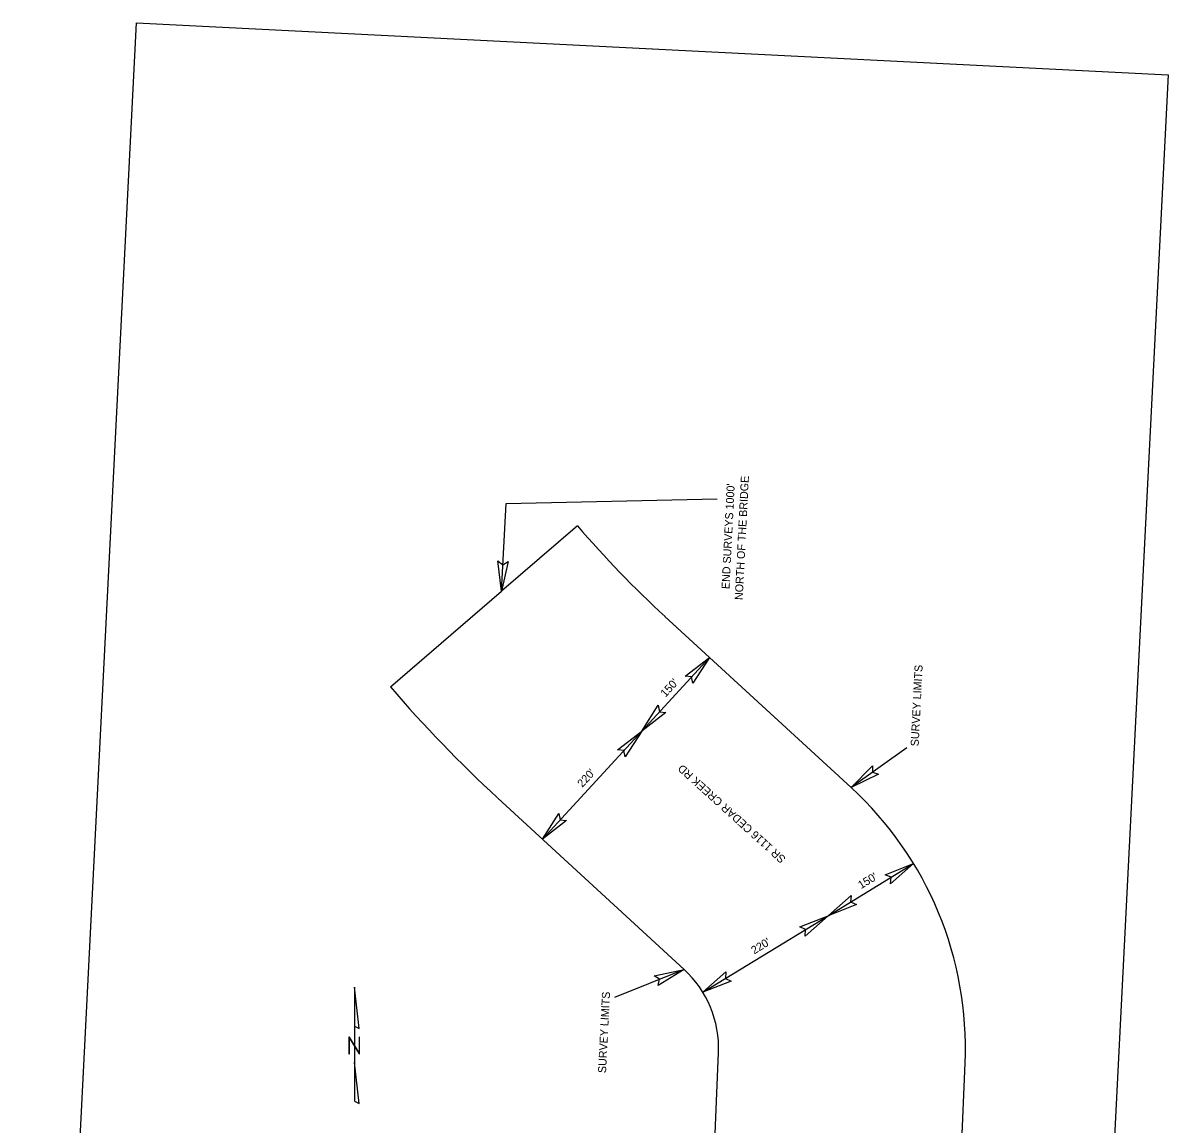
# Model space of a CAD drawing. Extents: x 2166842 to 2171409, y 841731 to 901457.
# Drawn here: x 2166842 to 2168559, y 843530 to 845181 of the extents above; entities that cross this region are included whole.
import ezdxf

# ---------------------------------------------------------------- set-up
doc = ezdxf.new("R2010")
doc.units = 0
doc.layers.add('Default', color=7, linetype='Continuous')
doc.layers.add('Prop Terminator CELL', color=7, linetype='Continuous')

# ---------------------------------------------------------------- blocks, each defined once
blk = doc.blocks.new('CTL NORTH ARROW')
at = {"layer": 'Default'}
for points in [[(0.00075, 1.74325), (0.00075, 0.57675), (0.1385, 0.508)], [(-0.16375, -0.247), (-0.15, -0.247), (-0.15, 0.2195), (0.1385, -0.247), (0.152, -0.247), (0.152, 0.2475), (0.1385, 0.2475), (0.1385, -0.21925), (-0.15, 0.2475), (-0.16375, 0.2475)], [(0.00075, -1.6735), (0.1385, -1.74225), (0.00075, -0.5075)]]:
    blk.add_lwpolyline(points, close=True, dxfattribs=at)
blk.add_lwpolyline([(0.00075, 0.57675), (0.00075, -0.5075)], dxfattribs=at)

msp = doc.modelspace()

# ---------------------------------------------------------------- linework, layer by layer
at = {"layer": 'Default'}
for p, q in [((2167560.1, 844329), (2167566.7, 844460.7)), ((2167566.7, 844460.7), (2167883.2, 844467.6)), ((2167673.7, 844426.9), (2167560.1, 844329)), ((2167393.4, 844185.5), (2167560.1, 844329)), ((2168083.9, 844034.7), (2167804.6, 844291.3)), ((2167770.1, 844119.3), (2167871.6, 844229.8)), ((2167621.2, 843957.3), (2167770.1, 844119.3)), ((2168167.7, 844094.5), (2168083.9, 844034.7)), ((2167833.6, 843762.3), (2167554.3, 844018.8)), ((2168049.5, 843842.7), (2168177.5, 843921)), ((2167861.8, 843727.9), (2168049.5, 843842.7)), ((2167833.6, 843762.3), (2167729.3, 843720.3)), ((2167842.5, 842642.3), (2167885.2, 843637.6)), ((2168212.2, 842626.4), (2168254.8, 843621.8))]:
    msp.add_line(p, q, dxfattribs=at)
msp.add_lwpolyline([(2167012.6, 845180.7), (2168559.1, 845102.7), (2168389, 841731), (2166842.5, 841809)], close=True, dxfattribs=at)
for centre, radius, start, end in [((2168931.3, 845509.9), 1659.6, 220.7334, 227.2593), ((2168931.3, 845509.9), 2029.6, 220.7334, 227.2593), ((2167725.3, 843644.5), 530, 357.5461, 47.426), ((2167725.3, 843644.5), 160, 357.5461, 47.426)]:
    msp.add_arc(centre, radius, start, end, dxfattribs=at)
at = {"layer": 'Prop Terminator CELL'}
for points in [[(2167570.1, 844373.6), (2167560.1, 844329), (2167554.4, 844374.6), (2167562.1, 844368.5)], [(2167835.4, 844201.9), (2167871.6, 844229.8), (2167846.8, 844191.1), (2167844.8, 844200.7)], [(2167806.2, 844147.2), (2167770.1, 844119.3), (2167794.8, 844158.1), (2167796.8, 844148.4)], [(2167733.9, 844091.5), (2167770.1, 844119.3), (2167745.4, 844080.6), (2167743.4, 844090.3)], [(2168125, 844054.6), (2168083.9, 844034.7), (2168116.1, 844067.5), (2168116.1, 844057.7)], [(2167657.4, 843985.2), (2167621.2, 843957.3), (2167646, 843996.1), (2167648, 843986.4)], [(2168135, 843904.1), (2168177.5, 843921), (2168143, 843890.5), (2168143.8, 843900.4)], [(2168091.9, 843859.6), (2168049.5, 843842.7), (2168083.9, 843873.2), (2168083.2, 843863.3)], [(2168007.1, 843825.9), (2168049.5, 843842.7), (2168015.1, 843812.3), (2168015.8, 843822.1)], [(2167788.9, 843752.7), (2167833.6, 843762.3), (2167794.6, 843738), (2167796.9, 843747.5)], [(2167904.3, 843744.8), (2167861.8, 843727.9), (2167896.2, 843758.4), (2167895.5, 843748.5)]]:
    msp.add_lwpolyline(points, close=True, dxfattribs=at)

# ---------------------------------------------------------------- block references
at = {"layer": 'Default', "xscale": 50.00000000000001, "yscale": 50.000000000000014, "rotation": -5.073493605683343e-12}
msp.add_blockref('CTL NORTH ARROW', (2167339.4, 843648.3), dxfattribs=at)

# ---------------------------------------------------------------- texts
at = {"layer": 'Default'}
for s, rotation, p in [("END SURVEYS 1000'", 87.1116, (2167901.6, 844332)), ('NORTH OF THE BRIDGE', 87.1116, (2167921.4, 844315.6)), ('SURVEY LIMITS', 87.1116, (2168185.1, 844096.4)), ("150'", 47.426, (2167805.7, 844169.3)), ("220'", 47.426, (2167681.1, 844034.2)), ('SR 1116 CEDAR CREEK RD', 137.801, (2167986.9, 843929.1)), ("150'", 31.4501, (2168098.8, 843882.4)), ("220'", 31.4501, (2167938.6, 843784.5)), ('SURVEY LIMITS', 87.1116, (2167716.5, 843606.6))]:
    msp.add_text(s, height=12, rotation=rotation, dxfattribs=at).set_placement(p)

doc.saveas('drawing.dxf')
